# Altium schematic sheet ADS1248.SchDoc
size A
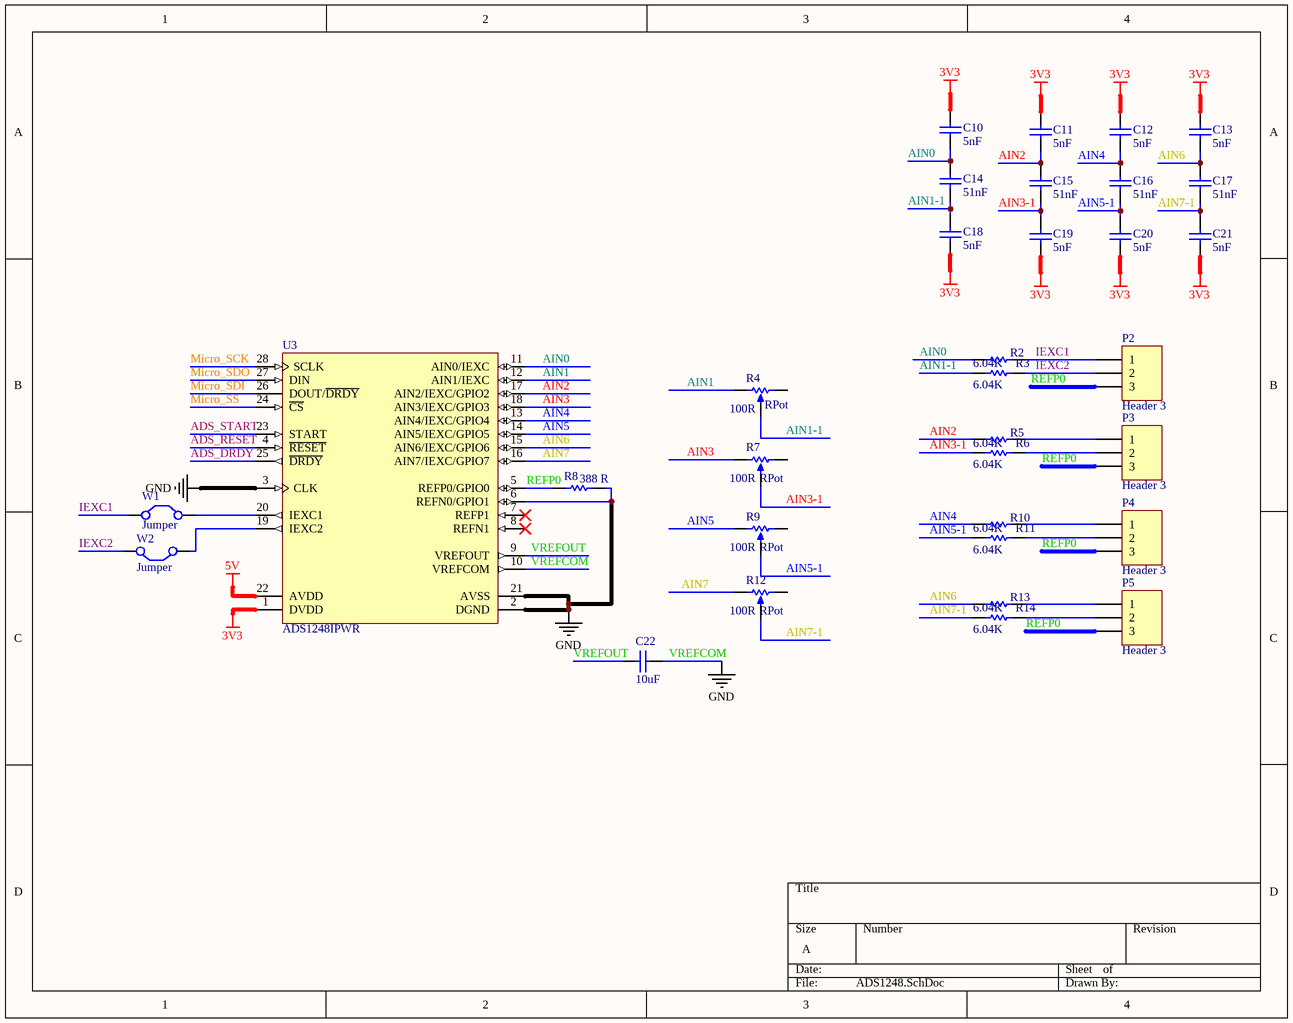
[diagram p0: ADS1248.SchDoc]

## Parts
C10  5nF  [0603-CAP]
C11  5nF  [0603-CAP]
C12  5nF  [0603-CAP]
C13  5nF  [0603-CAP]
C14  51nF  [0603-CAP]
C15  51nF  [0603-CAP]
C16  51nF  [0603-CAP]
C17  51nF  [0603-CAP]
C18  5nF  [0603-CAP]
C19  5nF  [0603-CAP]
C20  5nF  [0603-CAP]
C21  5nF  [0603-CAP]
C22  10uF  [0603-CAP]
P2  Header 3  [PHOENIX-3]
P3  Header 3  [PHOENIX-3]
P4  Header 3  [PHOENIX-3]
P5  Header 3  [PHOENIX-3]
R2  6.04K  [0603-RES]
R3  6.04K  [0603-RES]
R4  RPot  value 100R  [POT-MOL]
R5  6.04K  [0603-RES]
R6  6.04K  [0603-RES]
R7  RPot  value 100R  [POT-MOL]
R8  388 R  [0603-RES]
R9  RPot  value 100R  [POT-MOL]
R10  6.04K  [0603-RES]
R11  6.04K  [0603-RES]
R12  RPot  value 100R  [POT-MOL]
R13  6.04K  [0603-RES]
R14  6.04K  [0603-RES]
U3  ADS1248IPWR  [TI-PW28_N]
W1  Jumper  [HDR1X2]
W2  Jumper  [HDR1X2]

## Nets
3V3: C10.2 C11.2 C12.2 C13.2 C18.1 C19.1 C20.1 C21.1 U3.1(DVDD)
5V: U3.22(AVDD)
VREFCOM: C22.1 R8.1 U3.2(DGND) U3.3(CLK) U3.6(REFN0/GPIO1) U3.10(VREFCOM) U3.21(AVSS)  [also labelled GND]
ADS_DRDY: U3.25(~{DRDY})
ADS_RESET: U3.4(~{RESET})
ADS_START: U3.23(START)
AIN0: C10.1 C14.2 R2.1 U3.11(AIN0/IEXC)
AIN1: R4.1(TOP) U3.12(AIN1/IEXC)
AIN1-1: C14.1 C18.2 R3.1 R4.3(TAP)
AIN2: C11.1 C15.2 R5.1 U3.17(AIN2/IEXC/GPIO2)
AIN3: R7.1(TOP) U3.18(AIN3/IEXC/GPIO3)
AIN3-1: C15.1 C19.2 R6.1 R7.3(TAP)
AIN4: C12.1 C16.2 R10.1 U3.13(AIN4/IEXC/GPIO4)
AIN5: R9.1(TOP) U3.14(AIN5/IEXC/GPIO5)
AIN5-1: C16.1 C20.2 R9.3(TAP) R11.1
AIN6: C13.1 C17.2 R13.1 U3.15(AIN6/IEXC/GPIO6)
AIN7: R12.1(TOP) U3.16(AIN7/IEXC/GPIO7)
AIN7-1: C17.1 C21.2 R12.3(TAP) R14.1
IEXC1: P2.1 R2.2 W1.1(C1)
IEXC2: P2.2 R3.2 W2.2(C2)
Micro_SCK: U3.28(SCLK)
Micro_SDI: U3.26(DOUT/~{DRDY})
Micro_SDO: U3.27(DIN)
Micro_SS: U3.24(~{CS})
REFP0: P2.3 P3.3 P4.3 P5.3 R8.2 U3.5(REFP0/GPIO0)
VREFOUT: C22.2 U3.9(VREFOUT)
NetP3_1: P3.1 R5.2
NetP3_2: P3.2 R6.2
NetP4_1: P4.1 R10.2
NetP4_2: P4.2 R11.2
NetP5_1: P5.1 R13.2
NetP5_2: P5.2 R14.2
NetU3_19: U3.19(IEXC2) W2.1(C1)
NetU3_20: U3.20(IEXC1) W1.2(C2)

Not connected (* = marked no-connect by the designer): R4 2(BOT); R7 2(BOT); R9 2(BOT); R12 2(BOT); U3 7(REFP1)* 8(REFN1)*

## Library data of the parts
C10-C22 = Cap: Capacitor
P2-P5 = Header 3: Header, 3-Pin
R2 R3 R5 R6 R8 R10 R11 R13 R14 = Res: Resistor
R4 R7 R9 R12 = RPot: Potentiometer; Sim Note: Enter the Resistance value and the set point into parameter fields.; Set Position: 0.5
U3 = ADS1248IPWR: Precision 24-Bit ADC with Integrated Low Noise PGA (48 nV at a Gain of 128), -40 to 105 degC, 28-pin SOP (PW28), Green (RoHS & no Sb/Br); Manufacturer: Texas Instruments; # Input Channels: 7; Analog Voltage AV/DD(Max)(V): 5.25; Analog Voltage AV/DD(Min)(V): 2.7; Architecture: Delta-Sigma; Interface: Serial SPI; Resolution(Bits): 24; Sample Rate (max)(SPS): 2k; SubFamily: Precision ADC (<=10MSPS)
W1 W2 = Jumper: Jumper Wire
